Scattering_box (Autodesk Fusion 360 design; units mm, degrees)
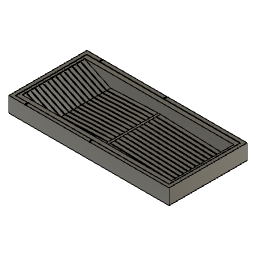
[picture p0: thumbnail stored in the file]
sketch "Floor" plane through (0, 0, 0) normal (0, 0, 1) x axis (1, 0, 0)
  line L1 (700, 0) -> (0, 0)
  line L2 (700, 305.6) -> (700, 0)
  line L3 (0, 305.6) -> (700, 305.6)
  line L4 (0, 0) -> (0, 305.6)
  point P1 (0, 0)
  point P2 (0, 0)
  point P3 (700, 0)
  point P5 (0, 305.6)
  horizontal L1
  vertical L2
  horizontal L3
  vertical L4
  coincident P1 P2
  dimension "d1" distance P2 P3 = 700
  dimension "d2" distance P2 P5 = 305.6
extrude "Extrude1" new body sketch "Floor" along normal blind 10
sketch "Wall around" plane through (0, 0, 10) normal (0, 0, 1) x axis (-1, 0, 0)
  line L1 (0, 0) -> (0, -305.6)
  line L2 (-700, 0) -> (0, 0)
  line L3 (-700, -305.6) -> (-700, 0)
  line L4 (0, -305.6) -> (-700, -305.6)
  line L5 (-690, -10) -> (-10, -10)
  line L6 (-690, -295.6) -> (-690, -10)
  line L7 (-10, -295.6) -> (-690, -295.6)
  line L8 (-10, -10) -> (-10, -295.6)
  point P8 (-690, -295.6)
  point P9 (-10, -295.6)
  dimension "d5" = -10
  dimension "d75" distance P8 P9 = 680
extrude "Extrude2" add sketch "Wall around" along normal blind 58
sketch "Side to extrude" plane through (0, 0, 0) normal (0, -1, 0) x axis (1, 0, 0)
  line L1 (700, 0) -> (0, 0)
  line L2 (700, 68) -> (700, 0)
  line L3 (0, 68) -> (700, 68)
  line L4 (0, 0) -> (0, 68)
  line L5 (10, 0) -> (0, 0)
  line L6 (10, 64.9115) -> (10, 0)
  line L7 (0, 64.9115) -> (10, 64.9115)
  line L8 (0, 0) -> (0, 64.9115)
  line L9 (700, 10) -> (0, 10)
  line L10 (127.758, 10) -> (10, 64.9115)
  line L11 (350, 0) -> (350, 68)
  line L12 (345, 0) -> (345, 68)
  line L13 (355, 0) -> (355, 68)
  line L14 (355, 20) -> (345, 20)
  line L15 (690, 0) -> (690, 68)
  line L16 (690, 7) -> (355, 20)
  line L17 (612.6923, 10) -> (690, 10)
  line L18 (690, 7) -> (690, 10)
  line L19 (127.758, 10) -> (345, 20)
  line L20 (10, 10) -> (10, 64.9115)
  line L21 (127.758, 10) -> (10, 10)
  line L22 (612.6923, 10) -> (127.758, 10)
  line L23 (300, 20) -> (345, 20)
  line L24 (300, 40) -> (300, 20)
  line L25 (400, 40) -> (300, 40)
  line L26 (400, 20) -> (400, 40)
  line L27 (300, 20) -> (400, 20)
  point P2 (0, 0)
  point P6 (0, 0)
  point P10 (0, 10)
  point P12 (127.758, 10)
  point P13 (350, 68)
  point P14 (350, 0)
  point P19 (345, 20)
  point P20 (355, 20)
  point P21 (690, 68)
  point P22 (690, 0)
  point P23 (690, 7)
  point P24 (690, 7)
  point P25 (690, 10)
  point P26 (612.6923, 10)
  point P27 (690, 7)
  point P28 (10, 10)
  point P7 (10, 0)
  horizontal L5
  vertical L6
  horizontal L7
  vertical L8
  coincident P2 P6
  coincident L4 P10
  perpendicular L4 L9
  coincident L9 P12
  midpoint L3 P13
  midpoint L1 P14
  coincident L12 P19
  coincident L13 P20
  perpendicular L13 L14
  coincident L3 P21
  coincident L1 P22
  perpendicular L1 L15
  coincident L15 P23
  coincident P23 P24
  coincident L15 P25
  coincident L9 P25
  coincident L16 P26
  coincident L9 P26
  coincident P23 P27
  coincident L6 P28
  coincident L9 P28
  perpendicular L12 L23
  perpendicular L23 L24
  perpendicular L24 L25
  perpendicular L25 L26
  perpendicular L24 L27
  dimension "d8" distance P6 P7 = 10
  dimension "d9" distance L1 L9 = 10
  dimension "d10" angle L9 L10 = 25
  dimension "d11" = 5
  dimension "d12" = -5
  dimension "d13" distance L3 L14 = 48
  dimension "d14" distance L2 L15 = 10
  dimension "d15" distance L9 P23 = 3
extrude "Extrude3" cut sketch "Side to extrude" profile of L16 L17 L18 blind -285.6 from offset -10
extrude "Extrude4" add sketch "Side to extrude" profile of L10 L14 L16 L19 L20 L21 L22 blind -285.6 from offset -10
work_plane "WorkPlane1" AlongDistance 7
sketch "ramp rails" plane through (26.6486, 0, 57.1481) normal (0.4226, 0, 0.9063) x axis (0, 1, 0)
  line L1 (10, -111.5619) -> (10, 18.3697)
  line L2 (295.6, 18.3697) -> (295.6, -111.5619)
  line L3 (30.3, 14.4071) -> (28.3, 14.4071)
  line L4 (30.3, -111.7503) -> (30.3, 14.4071)
  line L5 (28.3, -111.7503) -> (30.3, -111.7503)
  line L6 (28.3, 14.4071) -> (28.3, -111.7503)
  line L7 (49.3, -111.7503) -> (49.3, 14.4071)
  line L8 (47.3, -111.7503) -> (49.3, -111.7503)
  line L9 (47.3, 14.4071) -> (47.3, -111.7503)
  line L10 (49.3, 14.4071) -> (47.3, 14.4071)
  line L11 (68.3, -111.7503) -> (68.3, 14.4071)
  line L12 (66.3, -111.7503) -> (68.3, -111.7503)
  line L13 (66.3, 14.4071) -> (66.3, -111.7503)
  line L14 (68.3, 14.4071) -> (66.3, 14.4071)
  line L15 (87.3, -111.7503) -> (87.3, 14.4071)
  line L16 (85.3, -111.7503) -> (87.3, -111.7503)
  line L17 (85.3, 14.4071) -> (85.3, -111.7503)
  line L18 (87.3, 14.4071) -> (85.3, 14.4071)
  line L19 (106.3, -111.7503) -> (106.3, 14.4071)
  line L20 (104.3, -111.7503) -> (106.3, -111.7503)
  line L21 (104.3, 14.4071) -> (104.3, -111.7503)
  line L22 (106.3, 14.4071) -> (104.3, 14.4071)
  line L23 (125.3, -111.7503) -> (125.3, 14.4071)
  line L24 (123.3, -111.7503) -> (125.3, -111.7503)
  line L25 (123.3, 14.4071) -> (123.3, -111.7503)
  line L26 (125.3, 14.4071) -> (123.3, 14.4071)
  line L27 (144.3, -111.7503) -> (144.3, 14.4071)
  line L28 (142.3, -111.7503) -> (144.3, -111.7503)
  line L29 (142.3, 14.4071) -> (142.3, -111.7503)
  line L30 (144.3, 14.4071) -> (142.3, 14.4071)
  line L31 (163.3, -111.7503) -> (163.3, 14.4071)
  line L32 (161.3, -111.7503) -> (163.3, -111.7503)
  line L33 (161.3, 14.4071) -> (161.3, -111.7503)
  line L34 (163.3, 14.4071) -> (161.3, 14.4071)
  line L35 (182.3, -111.7503) -> (182.3, 14.4071)
  line L36 (180.3, -111.7503) -> (182.3, -111.7503)
  line L37 (180.3, 14.4071) -> (180.3, -111.7503)
  line L38 (182.3, 14.4071) -> (180.3, 14.4071)
  line L39 (201.3, -111.7503) -> (201.3, 14.4071)
  line L40 (199.3, -111.7503) -> (201.3, -111.7503)
  line L41 (199.3, 14.4071) -> (199.3, -111.7503)
  line L42 (201.3, 14.4071) -> (199.3, 14.4071)
  line L43 (220.3, -111.7503) -> (220.3, 14.4071)
  line L44 (218.3, -111.7503) -> (220.3, -111.7503)
  line L45 (218.3, 14.4071) -> (218.3, -111.7503)
  line L46 (220.3, 14.4071) -> (218.3, 14.4071)
  line L47 (239.3, -111.7503) -> (239.3, 14.4071)
  line L48 (237.3, -111.7503) -> (239.3, -111.7503)
  line L49 (237.3, 14.4071) -> (237.3, -111.7503)
  line L50 (239.3, 14.4071) -> (237.3, 14.4071)
  line L51 (258.3, -111.7503) -> (258.3, 14.4071)
  line L52 (256.3, -111.7503) -> (258.3, -111.7503)
  line L53 (256.3, 14.4071) -> (256.3, -111.7503)
  line L54 (258.3, 14.4071) -> (256.3, 14.4071)
  line L55 (277.3, -111.7503) -> (277.3, 14.4071)
  line L56 (275.3, -111.7503) -> (277.3, -111.7503)
  line L57 (275.3, 14.4071) -> (275.3, -111.7503)
  line L58 (277.3, 14.4071) -> (275.3, 14.4071)
  line L59 (10, 18.3697) -> (295.6, 18.3697)
  point P6 (28.3, 14.4071)
  point P7 (30.3, 14.4071)
  horizontal L3
  vertical L4
  horizontal L5
  vertical L6
  dimension "d29" distance P6 P7 = 2
  dimension "d32" R-Pattern1-uDistance = 19
  dimension "d33" R-Pattern1-vDistance = 0
extrude "Extrude6" add sketch "ramp rails" profile of L3 L4 L5 L6 L7 L8 L9 L10 L11 L12 L13 L14 L15 L16 L17 L18 L19 L20 L21 L22 L23 L24 L25 L26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 along normal blind 1.8
sketch "hold up bar cut" plane through (0, 0, 0) normal (0, 1, 0) x axis (1, 0, 0)
  line L1 (700, 0) -> (0, 0)
  line L2 (700, -68) -> (700, 0)
  line L3 (0, -68) -> (700, -68)
  line L4 (0, 0) -> (0, -68)
  line L5 (59, -68) -> (55, -68)
  line L6 (59, -46) -> (59, -68)
  line L7 (55, -46) -> (59, -46)
  line L8 (55, -68) -> (55, -46)
  point P6 (55, -68)
  point P7 (55, -68)
  point P5 (0, -68)
  point P8 (59, -68)
  coincident L3 P6
  horizontal L5
  vertical L6
  horizontal L7
  vertical L8
  coincident P6 P7
  dimension "d23" distance P5 P6 = 55
  dimension "d24" distance P7 P8 = 4
  dimension "d66" distance L3 L7 = 22
extrude "Extrude5" cut sketch "hold up bar cut" profile of L3 L5 L6 L7 L8 no distance stored
sketch "post ramp rails" plane through (-0.1892, 0, 4.1104) normal (-0.046, 0, 0.9989) x axis (0, -1, 0)
  line L1 (-275.3, 128.0827) -> (-275.3, 128.2954)
  line L2 (-258.3, 128.0827) -> (-275.3, 128.0827)
  line L3 (-258.3, 128.2954) -> (-258.3, 128.0827)
  line L4 (-256.3, 128.2954) -> (-258.3, 128.2954)
  line L5 (-256.3, 128.0827) -> (-256.3, 128.2954)
  line L6 (-239.3, 128.0827) -> (-256.3, 128.0827)
  line L7 (-239.3, 128.2954) -> (-239.3, 128.0827)
  line L8 (-237.3, 128.2954) -> (-239.3, 128.2954)
  line L9 (-237.3, 128.0827) -> (-237.3, 128.2954)
  line L10 (-220.3, 128.0827) -> (-237.3, 128.0827)
  line L11 (-220.3, 128.2954) -> (-220.3, 128.0827)
  line L12 (-218.3, 128.2954) -> (-220.3, 128.2954)
  line L13 (-218.3, 128.0827) -> (-218.3, 128.2954)
  line L14 (-201.3, 128.0827) -> (-218.3, 128.0827)
  line L15 (-201.3, 128.2954) -> (-201.3, 128.0827)
  line L16 (-199.3, 128.2954) -> (-201.3, 128.2954)
  line L17 (-199.3, 128.0827) -> (-199.3, 128.2954)
  line L18 (-182.3, 128.0827) -> (-199.3, 128.0827)
  line L19 (-182.3, 128.2954) -> (-182.3, 128.0827)
  line L20 (-180.3, 128.2954) -> (-182.3, 128.2954)
  line L21 (-180.3, 128.0827) -> (-180.3, 128.2954)
  line L22 (-163.3, 128.0827) -> (-180.3, 128.0827)
  line L23 (-163.3, 128.2954) -> (-163.3, 128.0827)
  line L24 (-161.3, 128.2954) -> (-163.3, 128.2954)
  line L25 (-161.3, 128.0827) -> (-161.3, 128.2954)
  line L26 (-144.3, 128.0827) -> (-161.3, 128.0827)
  line L27 (-144.3, 128.2954) -> (-144.3, 128.0827)
  line L28 (-142.3, 128.2954) -> (-144.3, 128.2954)
  line L29 (-142.3, 128.0827) -> (-142.3, 128.2954)
  line L30 (-125.3, 128.0827) -> (-142.3, 128.0827)
  line L31 (-125.3, 128.2954) -> (-125.3, 128.0827)
  line L32 (-123.3, 128.2954) -> (-125.3, 128.2954)
  line L33 (-123.3, 128.0827) -> (-123.3, 128.2954)
  line L34 (-106.3, 128.0827) -> (-123.3, 128.0827)
  line L35 (-106.3, 128.2954) -> (-106.3, 128.0827)
  line L36 (-104.3, 128.2954) -> (-106.3, 128.2954)
  line L37 (-104.3, 128.0827) -> (-104.3, 128.2954)
  line L38 (-87.3, 128.0827) -> (-104.3, 128.0827)
  line L39 (-87.3, 128.2954) -> (-87.3, 128.0827)
  line L40 (-85.3, 128.2954) -> (-87.3, 128.2954)
  line L41 (-85.3, 128.0827) -> (-85.3, 128.2954)
  line L42 (-68.3, 128.0827) -> (-85.3, 128.0827)
  line L43 (-68.3, 128.2954) -> (-68.3, 128.0827)
  line L44 (-66.3, 128.2954) -> (-68.3, 128.2954)
  line L45 (-66.3, 128.0827) -> (-66.3, 128.2954)
  line L46 (-49.3, 128.0827) -> (-66.3, 128.0827)
  line L47 (-49.3, 128.2954) -> (-49.3, 128.0827)
  line L48 (-47.3, 128.2954) -> (-49.3, 128.2954)
  line L49 (-47.3, 128.0827) -> (-47.3, 128.2954)
  line L50 (-30.3, 128.0827) -> (-47.3, 128.0827)
  line L51 (-30.3, 128.2954) -> (-30.3, 128.0827)
  line L52 (-28.3, 128.2954) -> (-30.3, 128.2954)
  line L53 (-28.3, 128.0827) -> (-28.3, 128.2954)
  line L54 (-10, 128.0827) -> (-28.3, 128.0827)
  line L55 (-10, 345.5547) -> (-10, 128.0827)
  line L56 (-295.6, 128.0827) -> (-295.6, 345.5547)
  line L57 (-277.3, 128.2954) -> (-277.3, 128.0827)
  line L58 (-275.3, 128.2954) -> (-277.3, 128.2954)
  line L59 (-295.6, 692.397) -> (-295.6, 62.0644)
  line L60 (-277.3, 128.2954) -> (-275.3, 128.2954)
  line L61 (-277.3, 345.5593) -> (-277.3, 128.2954)
  line L62 (-275.3, 345.5593) -> (-277.3, 345.5593)
  line L63 (-275.3, 128.2954) -> (-275.3, 345.5593)
  line L64 (-256.3, 345.5593) -> (-258.3, 345.5593)
  line L65 (-256.3, 128.2954) -> (-256.3, 345.5593)
  line L66 (-258.3, 345.5593) -> (-258.3, 128.2954)
  line L67 (-258.3, 128.2954) -> (-256.3, 128.2954)
  line L68 (-237.3, 345.5593) -> (-239.3, 345.5593)
  line L69 (-237.3, 128.2954) -> (-237.3, 345.5593)
  line L70 (-239.3, 345.5593) -> (-239.3, 128.2954)
  line L71 (-239.3, 128.2954) -> (-237.3, 128.2954)
  line L72 (-218.3, 345.5593) -> (-220.3, 345.5593)
  line L73 (-218.3, 128.2954) -> (-218.3, 345.5593)
  line L74 (-220.3, 345.5593) -> (-220.3, 128.2954)
  line L75 (-220.3, 128.2954) -> (-218.3, 128.2954)
  line L76 (-199.3, 345.5593) -> (-201.3, 345.5593)
  line L77 (-199.3, 128.2954) -> (-199.3, 345.5593)
  line L78 (-201.3, 345.5593) -> (-201.3, 128.2954)
  line L79 (-201.3, 128.2954) -> (-199.3, 128.2954)
  line L80 (-180.3, 345.5593) -> (-182.3, 345.5593)
  line L81 (-180.3, 128.2954) -> (-180.3, 345.5593)
  line L82 (-182.3, 345.5593) -> (-182.3, 128.2954)
  line L83 (-182.3, 128.2954) -> (-180.3, 128.2954)
  line L84 (-161.3, 345.5593) -> (-163.3, 345.5593)
  line L85 (-161.3, 128.2954) -> (-161.3, 345.5593)
  line L86 (-163.3, 345.5593) -> (-163.3, 128.2954)
  line L87 (-163.3, 128.2954) -> (-161.3, 128.2954)
  line L88 (-142.3, 345.5593) -> (-144.3, 345.5593)
  line L89 (-142.3, 128.2954) -> (-142.3, 345.5593)
  line L90 (-144.3, 345.5593) -> (-144.3, 128.2954)
  line L91 (-144.3, 128.2954) -> (-142.3, 128.2954)
  line L92 (-123.3, 345.5593) -> (-125.3, 345.5593)
  line L93 (-123.3, 128.2954) -> (-123.3, 345.5593)
  line L94 (-125.3, 345.5593) -> (-125.3, 128.2954)
  line L95 (-125.3, 128.2954) -> (-123.3, 128.2954)
  line L96 (-104.3, 345.5593) -> (-106.3, 345.5593)
  line L97 (-104.3, 128.2954) -> (-104.3, 345.5593)
  line L98 (-106.3, 345.5593) -> (-106.3, 128.2954)
  line L99 (-106.3, 128.2954) -> (-104.3, 128.2954)
  line L100 (-85.3, 345.5593) -> (-87.3, 345.5593)
  line L101 (-85.3, 128.2954) -> (-85.3, 345.5593)
  line L102 (-87.3, 345.5593) -> (-87.3, 128.2954)
  line L103 (-87.3, 128.2954) -> (-85.3, 128.2954)
  line L104 (-66.3, 345.5593) -> (-68.3, 345.5593)
  line L105 (-66.3, 128.2954) -> (-66.3, 345.5593)
  line L106 (-68.3, 345.5593) -> (-68.3, 128.2954)
  line L107 (-68.3, 128.2954) -> (-66.3, 128.2954)
  line L108 (-47.3, 345.5593) -> (-49.3, 345.5593)
  line L109 (-47.3, 128.2954) -> (-47.3, 345.5593)
  line L110 (-49.3, 345.5593) -> (-49.3, 128.2954)
  line L111 (-49.3, 128.2954) -> (-47.3, 128.2954)
  line L112 (-28.3, 345.5593) -> (-30.3, 345.5593)
  line L113 (-28.3, 128.2954) -> (-28.3, 345.5593)
  line L114 (-30.3, 345.5593) -> (-30.3, 128.2954)
  line L115 (-30.3, 128.2954) -> (-28.3, 128.2954)
  point P2 (-275.3, 128.2954)
  point P64 (-275.3, 128.2954)
  horizontal L60
  vertical L61
  horizontal L62
  vertical L63
  coincident P2 P64
  dimension "d39" R-Pattern1-uDistance = 19
  dimension "d40" R-Pattern1-vDistance = 0
extrude "Extrude7" add sketch "post ramp rails" profile of L4 L8 L12 L16 L20 L24 L28 L32 L36 L40 L44 L48 L52 L58 L60 L61 L62 L63 L64 L65 L66 L67 L68 L69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 along normal blind 1.8
sketch "detector rails" plane through (1.3087, 0, 33.7253) normal (0.0388, 0, 0.9992) x axis (0, 1, 0)
  line L1 (10, -689.2096) -> (10, -353.9575)
  line L2 (295.6, -353.9575) -> (295.6, -689.2096)
  line L3 (30.3, -353.9573) -> (28.3, -353.9573)
  line L4 (30.3, -689.9999) -> (30.3, -353.9573)
  line L5 (28.3, -689.9999) -> (30.3, -689.9999)
  line L6 (28.3, -353.9573) -> (28.3, -689.9999)
  line L7 (49.3, -689.9999) -> (49.3, -353.9573)
  line L8 (47.3, -353.9573) -> (47.3, -689.9999)
  line L9 (49.3, -353.9573) -> (47.3, -353.9573)
  line L10 (47.3, -689.9999) -> (49.3, -689.9999)
  line L11 (68.3, -689.9999) -> (68.3, -353.9573)
  line L12 (66.3, -353.9573) -> (66.3, -689.9999)
  line L13 (68.3, -353.9573) -> (66.3, -353.9573)
  line L14 (66.3, -689.9999) -> (68.3, -689.9999)
  line L15 (87.3, -689.9999) -> (87.3, -353.9573)
  line L16 (85.3, -353.9573) -> (85.3, -689.9999)
  line L17 (87.3, -353.9573) -> (85.3, -353.9573)
  line L18 (85.3, -689.9999) -> (87.3, -689.9999)
  line L19 (106.3, -689.9999) -> (106.3, -353.9573)
  line L20 (104.3, -353.9573) -> (104.3, -689.9999)
  line L21 (106.3, -353.9573) -> (104.3, -353.9573)
  line L22 (104.3, -689.9999) -> (106.3, -689.9999)
  line L23 (125.3, -689.9999) -> (125.3, -353.9573)
  line L24 (123.3, -353.9573) -> (123.3, -689.9999)
  line L25 (125.3, -353.9573) -> (123.3, -353.9573)
  line L26 (123.3, -689.9999) -> (125.3, -689.9999)
  line L27 (144.3, -689.9999) -> (144.3, -353.9573)
  line L28 (142.3, -353.9573) -> (142.3, -689.9999)
  line L29 (144.3, -353.9573) -> (142.3, -353.9573)
  line L30 (142.3, -689.9999) -> (144.3, -689.9999)
  line L31 (163.3, -689.9999) -> (163.3, -353.9573)
  line L32 (161.3, -353.9573) -> (161.3, -689.9999)
  line L33 (163.3, -353.9573) -> (161.3, -353.9573)
  line L34 (161.3, -689.9999) -> (163.3, -689.9999)
  line L35 (182.3, -689.9999) -> (182.3, -353.9573)
  line L36 (180.3, -353.9573) -> (180.3, -689.9999)
  line L37 (182.3, -353.9573) -> (180.3, -353.9573)
  line L38 (180.3, -689.9999) -> (182.3, -689.9999)
  line L39 (201.3, -689.9999) -> (201.3, -353.9573)
  line L40 (199.3, -353.9573) -> (199.3, -689.9999)
  line L41 (201.3, -353.9573) -> (199.3, -353.9573)
  line L42 (199.3, -689.9999) -> (201.3, -689.9999)
  line L43 (220.3, -689.9999) -> (220.3, -353.9573)
  line L44 (218.3, -353.9573) -> (218.3, -689.9999)
  line L45 (220.3, -353.9573) -> (218.3, -353.9573)
  line L46 (218.3, -689.9999) -> (220.3, -689.9999)
  line L47 (239.3, -689.9999) -> (239.3, -353.9573)
  line L48 (237.3, -353.9573) -> (237.3, -689.9999)
  line L49 (239.3, -353.9573) -> (237.3, -353.9573)
  line L50 (237.3, -689.9999) -> (239.3, -689.9999)
  line L51 (258.3, -689.9999) -> (258.3, -353.9573)
  line L52 (256.3, -353.9573) -> (256.3, -689.9999)
  line L53 (258.3, -353.9573) -> (256.3, -353.9573)
  line L54 (256.3, -689.9999) -> (258.3, -689.9999)
  line L55 (277.3, -689.9999) -> (277.3, -353.9573)
  line L56 (275.3, -353.9573) -> (275.3, -689.9999)
  line L57 (277.3, -353.9573) -> (275.3, -353.9573)
  line L58 (275.3, -689.9999) -> (277.3, -689.9999)
  point P6 (28.3, -353.9573)
  point P7 (28.3, -353.9573)
  point P2 (10, -353.9575)
  point P8 (30.3, -353.9573)
  horizontal L3
  vertical L4
  horizontal L5
  vertical L6
  coincident P6 P7
  dimension "d43" distance P2 P6 = 18.3
  dimension "d44" distance P7 P8 = 2
  dimension "d47" R-Pattern1-uDistance = 19
  dimension "d48" R-Pattern1-vDistance = 0
extrude "Extrude8" add sketch "detector rails" profile of L3 L4 L5 L6 L7 L8 L9 L10 L11 L12 L13 L14 L15 L16 L17 L18 L19 L20 L21 L22 L23 L24 L25 L26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 along normal blind 1.8
extrude "Extrude9" cut sketch "Side to extrude" profile of L14 L23 L24 L25 L26 L27 blind -285.6 from offset -10
extrude "Extrude10" add of existing geometry blind 10
extrude "Extrude11" add of existing geometry blind 10
sketch "Cartridge slot" plane through (0, -10, 0) normal (0, -1, 0) x axis (1, 0, 0)
  line L1 (55, 68) -> (55, 46)
  line L2 (0, 68) -> (55, 68)
  line L3 (0, 0) -> (0, 68)
  line L4 (700, 0) -> (0, 0)
  line L5 (700, 68) -> (700, 0)
  line L6 (59, 68) -> (700, 68)
  line L7 (59, 46) -> (59, 68)
  line L8 (55, 46) -> (59, 46)
  line L9 (350, 0) -> (350, 68)
  line L10 (348, 0) -> (348, 68)
  line L11 (352, 0) -> (352, 68)
  line L12 (348, 20) -> (352, 20)
  line L13 (352, 68) -> (348, 68)
  line L14 (352, 68) -> (348, 68)
  line L15 (352, 20) -> (352, 68)
  line L16 (348, 20) -> (352, 20)
  line L17 (348, 68) -> (348, 20)
  point P10 (350, 68)
  point P11 (350, 0)
  point P16 (352, 20)
  point P17 (352, 20)
  point P18 (348, 20)
  point P20 (352, 20)
  coincident L6 P10
  coincident L4 P11
  perpendicular L4 L9
  coincident L11 P16
  coincident P16 P17
  coincident L10 P18
  perpendicular L10 L12
  perpendicular L11 L13
  horizontal L14
  vertical L15
  horizontal L16
  vertical L17
  coincident P16 P20
  dimension "d67" distance L3 L9 = 350
  dimension "d68" = 2
  dimension "d69" = -2
  dimension "d70" distance L4 P16 = 20
extrude "Extrude13" cut sketch "Cartridge slot" profile of L6 L9 L10 L11 L12 L13 L14 L15 L16 L17 blind -305.6 from offset -10
sketch "Sketch10" plane through (0, 0, 0) normal (0, 0, -1) x axis (1, 0, 0)
  line L1 (0, -315.6) -> (0, 10)
  line L2 (700, -315.6) -> (0, -315.6)
  line L3 (700, 10) -> (700, -315.6)
  line L4 (0, 10) -> (700, 10)
  dimension "d74" distance L2 L4 = 325.6
extrude "Extrusion14" add of existing geometry blind 2
extrude "Extrusion15" add of existing geometry blind 15
extrude "Extrusion16" add of existing geometry blind 15
extrude "Extrusion17" add of existing geometry blind 15
extrude "Extrusion18" add of existing geometry blind 15
sketch "Esquisse11" plane through (0, 0, 70) normal (0, 0, 1) x axis (-1, 0, 0)
  line L1 (-348, -10) -> (-348, 0)
  line L2 (-59, -10) -> (-348, -10)
  line L3 (-59, 25) -> (-59, -10)
  line L4 (-715, 25) -> (-59, 25)
  line L5 (-715, -330.6) -> (-715, 25)
  line L6 (-59, -330.6) -> (-715, -330.6)
  line L7 (-59, -295.6) -> (-59, -330.6)
  line L8 (-348, -295.6) -> (-59, -295.6)
  line L9 (-348, -305.6) -> (-348, -295.6)
  line L10 (-352, -305.6) -> (-348, -305.6)
  line L11 (-352, -295.6) -> (-352, -305.6)
  line L12 (-690, -295.6) -> (-352, -295.6)
  line L13 (-690, -10) -> (-690, -295.6)
  line L14 (-352, -10) -> (-690, -10)
  line L15 (-352, 0) -> (-352, -10)
  line L16 (-348, 0) -> (-352, 0)
  line L17 (-700, -315) -> (0, -315)
  line L18 (-700, 10) -> (-700, -315)
  line L19 (0, 10) -> (-700, 10)
  line L20 (0, -315) -> (0, 10)
  horizontal L17
  vertical L18
  horizontal L19
  vertical L20
extrude "Extrusion19" cut sketch "Esquisse11" profile of L1 L2 L3 L7 L8 L9 L10 L11 L12 L13 L14 L15 L16 L17 L18 L19 against normal blind 2
sketch "Esquisse12" plane through (0, 0, 70) normal (0, 0, 1) x axis (-1, 0, 0)
  line L1 (-55, -330.6) -> (-55, -295.6)
  line L2 (15, -330.6) -> (-55, -330.6)
  line L3 (15, 25) -> (15, -330.6)
  line L4 (-55, 25) -> (15, 25)
  line L5 (-10, -10) -> (-55, -10)
  line L6 (-10, -295.6) -> (-10, -10)
  line L7 (-55, -295.6) -> (-10, -295.6)
sketch "Esquisse13" plane through (0, 0, 0) normal (0, 0, -1) x axis (1, 0, 0)
sketch "Esquisse20" plane through (0, 0, 70) normal (0, 0, 1) x axis (-1, 0, 0)
  line L1 (-55, -330.6) -> (-55, -295.6)
  line L2 (15, -330.6) -> (-55, -330.6)
  line L3 (15, 25) -> (15, -330.6)
  line L4 (-55, 25) -> (15, 25)
  line L5 (-55, -10) -> (-55, 25)
  line L6 (-10, -10) -> (-55, -10)
  line L7 (-10, -295.6) -> (-10, -10)
  line L8 (-55, -295.6) -> (-10, -295.6)
  line L9 (0, 0) -> (-55, 0)
  line L10 (0, -315) -> (0, 0)
  line L11 (-55, -315) -> (0, -315)
  line L12 (-10, -295.6) -> (-55, -295.6)
  line L13 (-55, -10) -> (-10, -10)
  line L14 (-55, -10) -> (-55, 0)
  point P10 (-55, 0)
  point P1 (0, 0)
  point P11 (0, 0)
  point P13 (-55, -315)
  point P2 (-55, -295.6)
  point P14 (-55, -295.6)
  point P9 (-10, -295.6)
  point P15 (-10, -295.6)
  point P8 (-10, -10)
  point P16 (-10, -10)
  point P7 (-55, -10)
  point P17 (-55, -10)
  coincident L5 P10
  coincident P1 P11
  perpendicular L5 L9
  perpendicular L2 L10
  coincident L1 P13
  perpendicular L1 L11
  coincident P2 P14
  coincident P9 P15
  coincident P8 P16
  coincident P7 P17
extrude "Extrusion20" cut sketch "Esquisse20" profile of L1 L5 L6 L7 L8 L9 L10 L11 L12 L13 L14 against normal blind 2
extrude "Extrusion21" cut of existing geometry blind -10
extrude "Extrusion22" cut of existing geometry blind -35
extrude "Extrusion23" cut of existing geometry blind -30
extrude "Extrusion24" cut of existing geometry blind -5
extrude "Extrusion25" cut of existing geometry blind -5
sketch "Esquisse21" plane through (0, 0, 20) normal (0, 0, 1) x axis (-1, 0, 0)
  line L1 (-345, -295.6) -> (-348, -295.6)
  line L2 (-345, -277.3) -> (-345, -295.6)
  line L3 (-305.855, -277.3) -> (-345, -277.3)
  line L4 (-305.855, -275.3) -> (-305.855, -277.3)
  line L5 (-345, -275.3) -> (-305.855, -275.3)
  line L6 (-345, -258.3) -> (-345, -275.3)
  line L7 (-305.855, -258.3) -> (-345, -258.3)
  line L8 (-305.855, -256.3) -> (-305.855, -258.3)
  line L9 (-345, -256.3) -> (-305.855, -256.3)
  line L10 (-345, -239.3) -> (-345, -256.3)
  line L11 (-305.855, -239.3) -> (-345, -239.3)
  line L12 (-305.855, -237.3) -> (-305.855, -239.3)
  line L13 (-345, -237.3) -> (-305.855, -237.3)
  line L14 (-345, -220.3) -> (-345, -237.3)
  line L15 (-305.855, -220.3) -> (-345, -220.3)
  line L16 (-305.855, -218.3) -> (-305.855, -220.3)
  line L17 (-345, -218.3) -> (-305.855, -218.3)
  line L18 (-345, -201.3) -> (-345, -218.3)
  line L19 (-305.855, -201.3) -> (-345, -201.3)
  line L20 (-305.855, -199.3) -> (-305.855, -201.3)
  line L21 (-345, -199.3) -> (-305.855, -199.3)
  line L22 (-345, -182.3) -> (-345, -199.3)
  line L23 (-305.855, -182.3) -> (-345, -182.3)
  line L24 (-305.855, -180.3) -> (-305.855, -182.3)
  line L25 (-345, -180.3) -> (-305.855, -180.3)
  line L26 (-345, -163.3) -> (-345, -180.3)
  line L27 (-305.855, -163.3) -> (-345, -163.3)
  line L28 (-305.855, -161.3) -> (-305.855, -163.3)
  line L29 (-345, -161.3) -> (-305.855, -161.3)
  line L30 (-345, -144.3) -> (-345, -161.3)
  line L31 (-305.855, -144.3) -> (-345, -144.3)
  line L32 (-305.855, -142.3) -> (-305.855, -144.3)
  line L33 (-345, -142.3) -> (-305.855, -142.3)
  line L34 (-345, -125.3) -> (-345, -142.3)
  line L35 (-305.855, -125.3) -> (-345, -125.3)
  line L36 (-305.855, -123.3) -> (-305.855, -125.3)
  line L37 (-345, -123.3) -> (-305.855, -123.3)
  line L38 (-345, -106.3) -> (-345, -123.3)
  line L39 (-305.855, -106.3) -> (-345, -106.3)
  line L40 (-305.855, -104.3) -> (-305.855, -106.3)
  line L41 (-345, -104.3) -> (-305.855, -104.3)
  line L42 (-345, -87.3) -> (-345, -104.3)
  line L43 (-305.855, -87.3) -> (-345, -87.3)
  line L44 (-305.855, -85.3) -> (-305.855, -87.3)
  line L45 (-345, -85.3) -> (-305.855, -85.3)
  line L46 (-345, -68.3) -> (-345, -85.3)
  line L47 (-305.855, -68.3) -> (-345, -68.3)
  line L48 (-305.855, -66.3) -> (-305.855, -68.3)
  line L49 (-345, -66.3) -> (-305.855, -66.3)
  line L50 (-345, -49.3) -> (-345, -66.3)
  line L51 (-305.855, -49.3) -> (-345, -49.3)
  line L52 (-305.855, -47.3) -> (-305.855, -49.3)
  line L53 (-345, -47.3) -> (-305.855, -47.3)
  line L54 (-345, -30.3) -> (-345, -47.3)
  line L55 (-305.855, -30.3) -> (-345, -30.3)
  line L56 (-305.855, -28.3) -> (-305.855, -30.3)
  line L57 (-345, -28.3) -> (-305.855, -28.3)
  line L58 (-345, -10) -> (-345, -28.3)
  line L59 (-348, -10) -> (-345, -10)
  line L60 (-348, 25) -> (-348, -10)
  line L61 (-352, 25) -> (-348, 25)
  line L62 (-352, -10) -> (-352, 25)
  line L63 (-355, -10) -> (-352, -10)
  line L64 (-355, -28.3) -> (-355, -10)
  line L65 (-400, -28.3) -> (-355, -28.3)
  line L66 (-400, -30.3) -> (-400, -28.3)
  line L67 (-355, -30.3) -> (-400, -30.3)
  line L68 (-355, -47.3) -> (-355, -30.3)
  line L69 (-400, -47.3) -> (-355, -47.3)
  line L70 (-400, -49.3) -> (-400, -47.3)
  line L71 (-355, -49.3) -> (-400, -49.3)
  line L72 (-355, -66.3) -> (-355, -49.3)
  line L73 (-400, -66.3) -> (-355, -66.3)
  line L74 (-400, -68.3) -> (-400, -66.3)
  line L75 (-355, -68.3) -> (-400, -68.3)
  line L76 (-355, -85.3) -> (-355, -68.3)
  line L77 (-400, -85.3) -> (-355, -85.3)
  line L78 (-400, -87.3) -> (-400, -85.3)
  line L79 (-355, -87.3) -> (-400, -87.3)
  line L80 (-355, -104.3) -> (-355, -87.3)
  line L81 (-400, -104.3) -> (-355, -104.3)
  line L82 (-400, -106.3) -> (-400, -104.3)
  line L83 (-355, -106.3) -> (-400, -106.3)
  line L84 (-355, -123.3) -> (-355, -106.3)
  line L85 (-400, -123.3) -> (-355, -123.3)
  line L86 (-400, -125.3) -> (-400, -123.3)
  line L87 (-355, -125.3) -> (-400, -125.3)
  line L88 (-355, -142.3) -> (-355, -125.3)
  line L89 (-400, -142.3) -> (-355, -142.3)
  line L90 (-400, -144.3) -> (-400, -142.3)
  line L91 (-355, -144.3) -> (-400, -144.3)
  line L92 (-355, -161.3) -> (-355, -144.3)
  line L93 (-400, -161.3) -> (-355, -161.3)
  line L94 (-400, -163.3) -> (-400, -161.3)
  line L95 (-355, -163.3) -> (-400, -163.3)
  line L96 (-355, -180.3) -> (-355, -163.3)
  line L97 (-400, -180.3) -> (-355, -180.3)
  line L98 (-400, -182.3) -> (-400, -180.3)
  line L99 (-355, -182.3) -> (-400, -182.3)
  line L100 (-355, -199.3) -> (-355, -182.3)
  line L101 (-400, -199.3) -> (-355, -199.3)
  line L102 (-400, -201.3) -> (-400, -199.3)
  line L103 (-355, -201.3) -> (-400, -201.3)
  line L104 (-355, -218.3) -> (-355, -201.3)
  line L105 (-400, -218.3) -> (-355, -218.3)
  line L106 (-400, -220.3) -> (-400, -218.3)
  line L107 (-355, -220.3) -> (-400, -220.3)
  line L108 (-355, -237.3) -> (-355, -220.3)
  line L109 (-400, -237.3) -> (-355, -237.3)
  line L110 (-400, -239.3) -> (-400, -237.3)
  line L111 (-355, -239.3) -> (-400, -239.3)
  line L112 (-355, -256.3) -> (-355, -239.3)
  line L113 (-400, -256.3) -> (-355, -256.3)
  line L114 (-400, -258.3) -> (-400, -256.3)
  line L115 (-355, -258.3) -> (-400, -258.3)
  line L116 (-355, -275.3) -> (-355, -258.3)
  line L117 (-400, -275.3) -> (-355, -275.3)
  line L118 (-400, -277.3) -> (-400, -275.3)
  line L119 (-355, -277.3) -> (-400, -277.3)
  line L120 (-355, -295.6) -> (-355, -277.3)
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  point P61 (-348, -10)
  point P128 (-348, -10)
  point P63 (-352, 25)
  point P126 (-352, 25)
  point P125 (-348, -330.6)
  point P132 (-348, -330.6)
  point P123 (-352, -295.6)
  point P130 (-352, -295.6)
  coincident P61 P128
  coincident P63 P126
  coincident P125 P132
  coincident P123 P130
extrude "Extrusion26" add sketch "Esquisse21" along normal blind 40
extrude "Extrusion27" cut of existing geometry blind -2
sketch "Esquisse22" plane through (0, 0, 20) normal (0, 0, 1) x axis (-1, 0, 0)
  line L1 (-345, -295.6) -> (-355, -295.6)
  line L2 (-345, -277.3) -> (-345, -295.6)
  line L3 (-305.855, -277.3) -> (-345, -277.3)
  line L4 (-305.855, -275.3) -> (-305.855, -277.3)
  line L5 (-345, -275.3) -> (-305.855, -275.3)
  line L6 (-345, -258.3) -> (-345, -275.3)
  line L7 (-305.855, -258.3) -> (-345, -258.3)
  line L8 (-305.855, -256.3) -> (-305.855, -258.3)
  line L9 (-345, -256.3) -> (-305.855, -256.3)
  line L10 (-345, -239.3) -> (-345, -256.3)
  line L11 (-305.855, -239.3) -> (-345, -239.3)
  line L12 (-305.855, -237.3) -> (-305.855, -239.3)
  line L13 (-345, -237.3) -> (-305.855, -237.3)
  line L14 (-345, -220.3) -> (-345, -237.3)
  line L15 (-305.855, -220.3) -> (-345, -220.3)
  line L16 (-305.855, -218.3) -> (-305.855, -220.3)
  line L17 (-345, -218.3) -> (-305.855, -218.3)
  line L18 (-345, -201.3) -> (-345, -218.3)
  line L19 (-305.855, -201.3) -> (-345, -201.3)
  line L20 (-305.855, -199.3) -> (-305.855, -201.3)
  line L21 (-345, -199.3) -> (-305.855, -199.3)
  line L22 (-345, -182.3) -> (-345, -199.3)
  line L23 (-305.855, -182.3) -> (-345, -182.3)
  line L24 (-305.855, -180.3) -> (-305.855, -182.3)
  line L25 (-345, -180.3) -> (-305.855, -180.3)
  line L26 (-345, -163.3) -> (-345, -180.3)
  line L27 (-305.855, -163.3) -> (-345, -163.3)
  line L28 (-305.855, -161.3) -> (-305.855, -163.3)
  line L29 (-345, -161.3) -> (-305.855, -161.3)
  line L30 (-345, -144.3) -> (-345, -161.3)
  line L31 (-305.855, -144.3) -> (-345, -144.3)
  line L32 (-305.855, -142.3) -> (-305.855, -144.3)
  line L33 (-345, -142.3) -> (-305.855, -142.3)
  line L34 (-345, -125.3) -> (-345, -142.3)
  line L35 (-305.855, -125.3) -> (-345, -125.3)
  line L36 (-305.855, -123.3) -> (-305.855, -125.3)
  line L37 (-345, -123.3) -> (-305.855, -123.3)
  line L38 (-345, -106.3) -> (-345, -123.3)
  line L39 (-305.855, -106.3) -> (-345, -106.3)
  line L40 (-305.855, -104.3) -> (-305.855, -106.3)
  line L41 (-345, -104.3) -> (-305.855, -104.3)
  line L42 (-345, -87.3) -> (-345, -104.3)
  line L43 (-305.855, -87.3) -> (-345, -87.3)
  line L44 (-305.855, -85.3) -> (-305.855, -87.3)
  line L45 (-345, -85.3) -> (-305.855, -85.3)
  line L46 (-345, -68.3) -> (-345, -85.3)
  line L47 (-305.855, -68.3) -> (-345, -68.3)
  line L48 (-305.855, -66.3) -> (-305.855, -68.3)
  line L49 (-345, -66.3) -> (-305.855, -66.3)
  line L50 (-345, -49.3) -> (-345, -66.3)
  line L51 (-305.855, -49.3) -> (-345, -49.3)
  line L52 (-305.855, -47.3) -> (-305.855, -49.3)
  line L53 (-345, -47.3) -> (-305.855, -47.3)
  line L54 (-345, -30.3) -> (-345, -47.3)
  line L55 (-305.855, -30.3) -> (-345, -30.3)
  line L56 (-305.855, -28.3) -> (-305.855, -30.3)
  line L57 (-345, -28.3) -> (-305.855, -28.3)
  line L58 (-345, -10) -> (-345, -28.3)
  line L59 (-348, -10) -> (-345, -10)
  line L60 (-348, 25) -> (-348, -10)
  line L61 (-352, 25) -> (-348, 25)
  line L62 (-352, -10) -> (-352, 25)
  line L63 (-355, -10) -> (-352, -10)
  line L64 (-355, -28.3) -> (-355, -10)
  line L65 (-400, -28.3) -> (-355, -28.3)
  line L66 (-400, -30.3) -> (-400, -28.3)
  line L67 (-355, -30.3) -> (-400, -30.3)
  line L68 (-355, -47.3) -> (-355, -30.3)
  line L69 (-400, -47.3) -> (-355, -47.3)
  line L70 (-400, -49.3) -> (-400, -47.3)
  line L71 (-355, -49.3) -> (-400, -49.3)
  line L72 (-355, -66.3) -> (-355, -49.3)
  line L73 (-400, -66.3) -> (-355, -66.3)
  line L74 (-400, -68.3) -> (-400, -66.3)
  line L75 (-355, -68.3) -> (-400, -68.3)
  line L76 (-355, -85.3) -> (-355, -68.3)
  line L77 (-400, -85.3) -> (-355, -85.3)
  line L78 (-400, -87.3) -> (-400, -85.3)
  line L79 (-355, -87.3) -> (-400, -87.3)
  line L80 (-355, -104.3) -> (-355, -87.3)
  line L81 (-400, -104.3) -> (-355, -104.3)
  line L82 (-400, -106.3) -> (-400, -104.3)
  line L83 (-355, -106.3) -> (-400, -106.3)
  line L84 (-355, -123.3) -> (-355, -106.3)
  line L85 (-400, -123.3) -> (-355, -123.3)
  line L86 (-400, -125.3) -> (-400, -123.3)
  line L87 (-355, -125.3) -> (-400, -125.3)
  line L88 (-355, -142.3) -> (-355, -125.3)
  line L89 (-400, -142.3) -> (-355, -142.3)
  line L90 (-400, -144.3) -> (-400, -142.3)
  line L91 (-355, -144.3) -> (-400, -144.3)
  line L92 (-355, -161.3) -> (-355, -144.3)
  line L93 (-400, -161.3) -> (-355, -161.3)
  line L94 (-400, -163.3) -> (-400, -161.3)
  line L95 (-355, -163.3) -> (-400, -163.3)
  line L96 (-355, -180.3) -> (-355, -163.3)
  line L97 (-400, -180.3) -> (-355, -180.3)
  line L98 (-400, -182.3) -> (-400, -180.3)
  line L99 (-355, -182.3) -> (-400, -182.3)
  line L100 (-355, -199.3) -> (-355, -182.3)
  line L101 (-400, -199.3) -> (-355, -199.3)
  line L102 (-400, -201.3) -> (-400, -199.3)
  line L103 (-355, -201.3) -> (-400, -201.3)
  line L104 (-355, -218.3) -> (-355, -201.3)
  line L105 (-400, -218.3) -> (-355, -218.3)
  line L106 (-400, -220.3) -> (-400, -218.3)
  line L107 (-355, -220.3) -> (-400, -220.3)
  line L108 (-355, -237.3) -> (-355, -220.3)
  line L109 (-400, -237.3) -> (-355, -237.3)
  line L110 (-400, -239.3) -> (-400, -237.3)
  line L111 (-355, -239.3) -> (-400, -239.3)
  line L112 (-355, -256.3) -> (-355, -239.3)
  line L113 (-400, -256.3) -> (-355, -256.3)
  line L114 (-400, -258.3) -> (-400, -256.3)
  line L115 (-355, -258.3) -> (-400, -258.3)
  line L116 (-355, -275.3) -> (-355, -258.3)
  line L117 (-400, -275.3) -> (-355, -275.3)
  line L118 (-400, -277.3) -> (-400, -275.3)
  line L119 (-355, -277.3) -> (-400, -277.3)
  line L120 (-355, -295.6) -> (-355, -277.3)
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  point P61 (-348, -10)
  point P124 (-348, -10)
  point P63 (-352, 25)
  point P122 (-352, 25)
  coincident P61 P124
  coincident P63 P122
extrude "Extrusion28" add sketch "Esquisse22" along normal blind 38
extrude "Extrusion29" add of existing geometry blind 12
extrude "Extrusion30" add of existing geometry blind 12
extrude "Extrusion31" add of existing geometry blind 10
extrude "Extrusion32" add of existing geometry blind 10
extrude "Extrusion33" add of existing geometry blind 10
extrude "Extrusion34" add of existing geometry blind 10
sketch "Esquisse23" plane through (0, 0, 68) normal (0, 0, 1) x axis (-1, 0, 0)
  line L1 (-700, 10) -> (-352, 10)
  line L2 (-700, -315) -> (-700, 10)
  line L3 (-352, -315) -> (-700, -315)
  line L4 (-352, -330.6) -> (-352, -315)
  line L5 (-348, -330.6) -> (-352, -330.6)
  line L6 (-348, -315) -> (-348, -330.6)
  line L7 (-59, -315) -> (-348, -315)
  line L8 (-59, -330.6) -> (-59, -315)
  line L9 (-55, -330.6) -> (-59, -330.6)
  line L10 (-55, -315) -> (-55, -330.6)
  line L11 (0, -315) -> (-55, -315)
  line L12 (0, 10) -> (0, -315)
  line L13 (-55, 10) -> (0, 10)
  line L14 (-55, 25) -> (-55, 10)
  line L15 (-59, 25) -> (-55, 25)
  line L16 (-59, 10) -> (-59, 25)
  line L17 (-348, 10) -> (-59, 10)
  line L18 (-348, 25) -> (-348, 10)
  line L19 (-352, 25) -> (-348, 25)
  line L20 (-352, 10) -> (-352, 25)
  line L21 (-10, -10) -> (-690, -10)
  line L22 (-10, -295.6) -> (-10, -10)
  line L23 (-690, -295.6) -> (-10, -295.6)
  line L24 (-690, -10) -> (-690, -295.6)
  line L25 (-59, -330.6) -> (-55, -330.6)
  line L26 (-59, -315) -> (-59, -330.6)
  line L27 (-55, -315) -> (-59, -315)
  line L28 (-55, -330.6) -> (-55, -315)
  line L29 (-352, -330.6) -> (-348, -330.6)
  line L30 (-352, -315) -> (-352, -330.6)
  line L31 (-348, -315) -> (-352, -315)
  line L32 (-348, -330.6) -> (-348, -315)
  line L33 (-59, 10) -> (-55, 10)
  line L34 (-59, 25) -> (-59, 10)
  line L35 (-55, 25) -> (-59, 25)
  line L36 (-55, 10) -> (-55, 25)
  line L37 (-352, 10) -> (-348, 10)
  line L38 (-352, 25) -> (-352, 10)
  line L39 (-348, 25) -> (-352, 25)
  line L40 (-348, 10) -> (-348, 25)
  point P9 (-59, -315)
  point P28 (-59, -315)
  point P11 (-55, -330.6)
  point P26 (-55, -330.6)
  point P5 (-352, -315)
  point P32 (-352, -315)
  point P7 (-348, -330.6)
  point P30 (-348, -330.6)
  point P17 (-59, 25)
  point P36 (-59, 25)
  point P15 (-55, 10)
  point P34 (-55, 10)
  point P21 (-352, 25)
  point P40 (-352, 25)
  point P19 (-348, 10)
  point P38 (-348, 10)
  horizontal L25
  vertical L26
  horizontal L27
  vertical L28
  coincident P9 P28
  coincident P11 P26
  horizontal L29
  vertical L30
  horizontal L31
  vertical L32
  coincident P5 P32
  coincident P7 P30
  horizontal L33
  vertical L34
  horizontal L35
  vertical L36
  coincident P17 P36
  coincident P15 P34
  horizontal L37
  vertical L38
  horizontal L39
  vertical L40
  coincident P21 P40
  coincident P19 P38
extrude "Extrusion35" add sketch "Esquisse23" profile of L4 L5 L6 L8 L9 L10 L14 L15 L16 L18 L19 L20 L25 L26 L27 L28 L29 L30 L31 L32 L33 L34 L35 L36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 along normal blind 1
sketch "Esquisse24" plane through (0, 0, 70) normal (0, 0, 1) x axis (-1, 0, 0)
  line L1 (0, 10) -> (-55, 10)
  line L2 (0, -315) -> (0, 10)
  line L3 (-55, -315) -> (0, -315)
  line L4 (-55, -330.6) -> (-55, -315)
  line L5 (15, -330.6) -> (-55, -330.6)
  line L6 (15, 25) -> (15, -330.6)
  line L7 (-55, 25) -> (15, 25)
  line L8 (-55, 10) -> (-55, 25)
sketch "Esquisse14" plane through (0, 0, 0) normal (0, 0, -1) x axis (1, 0, 0)
sketch "Esquisse15" plane through (0, 0, 70) normal (0, 0, 1) x axis (-1, 0, 0)
  line L1 (0, 25) -> (15, 25)
  line L2 (15, 25) -> (15, 10)
  point P2 (15, 25)
  point P5 (15, 25)
  point P3 (0, 25)
  point P4 (15, 10)
  horizontal L1
  vertical L2
  coincident P2 P5
  dimension "d88" distance P2 P3 = 15
  dimension "d89" distance P2 P4 = 15
sketch "Esquisse16" plane through (0, 0, 70) normal (0, 0, 1) x axis (-1, 0, 0)
  line L1 (0, -330.6) -> (15, -330.6)
  line L2 (0, -315.6) -> (0, -330.6)
  line L3 (15, -315.6) -> (0, -315.6)
  line L4 (15, -330.6) -> (15, -315.6)
  line L5 (-55, -315.6) -> (0, -315.6)
  line L6 (-55, -330.6) -> (-55, -315.6)
  line L7 (0, -330.6) -> (-55, -330.6)
  line L8 (0, -315.6) -> (0, -330.6)
  line L9 (15, -315.6) -> (0, -315.6)
  line L10 (15, 10) -> (15, -315.6)
  line L11 (0, 25) -> (-55, 25)
  point P2 (15, -330.6)
  point P6 (15, -330.6)
  point P8 (-55, -330.6)
  point P10 (-55, -330.6)
  point P12 (15, 10)
  point P13 (15, 10)
  point P14 (-55, 25)
  point P16 (-55, 25)
  point P3 (0, -330.6)
  point P5 (15, -315.6)
  horizontal L1
  vertical L2
  horizontal L3
  vertical L4
  coincident P2 P6
  horizontal L5
  vertical L6
  horizontal L7
  vertical L8
  coincident P8 P10
  horizontal L9
  vertical L10
  coincident P12 P13
  horizontal L11
  coincident P14 P16
  dimension "d90" distance P2 P3 = 15
  dimension "d91" distance P2 P5 = 15
sketch "Esquisse17" plane through (0, 0, 70) normal (0, 0, 1) x axis (1, 0, 0)
  line L1 (-15, 315.6) -> (0, 315.6)
  line L2 (0, 315) -> (55, 315)
  line L3 (10, 10) -> (55, 10)
  line L4 (10, 295.6) -> (10, 10)
  line L5 (55, 295.6) -> (10, 295.6)
  line L6 (55, 315) -> (55, 295.6)
  point P8 (55, 10)
  point P10 (55, 10)
  point P9 (10, 10)
  point P11 (10, 10)
  point P12 (10, 295.6)
  point P13 (10, 295.6)
  point P14 (55, 295.6)
  point P15 (55, 295.6)
  coincident P8 P10
  coincident P9 P11
  coincident P12 P13
  perpendicular L2 L4
  coincident P14 P15
sketch "Esquisse18" plane through (0, 0, 70) normal (0, 0, 1) x axis (1, 0, 0)
sketch "Esquisse19" plane through (0, 0, 70) normal (0, 0, 1) x axis (1, 0, 0)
